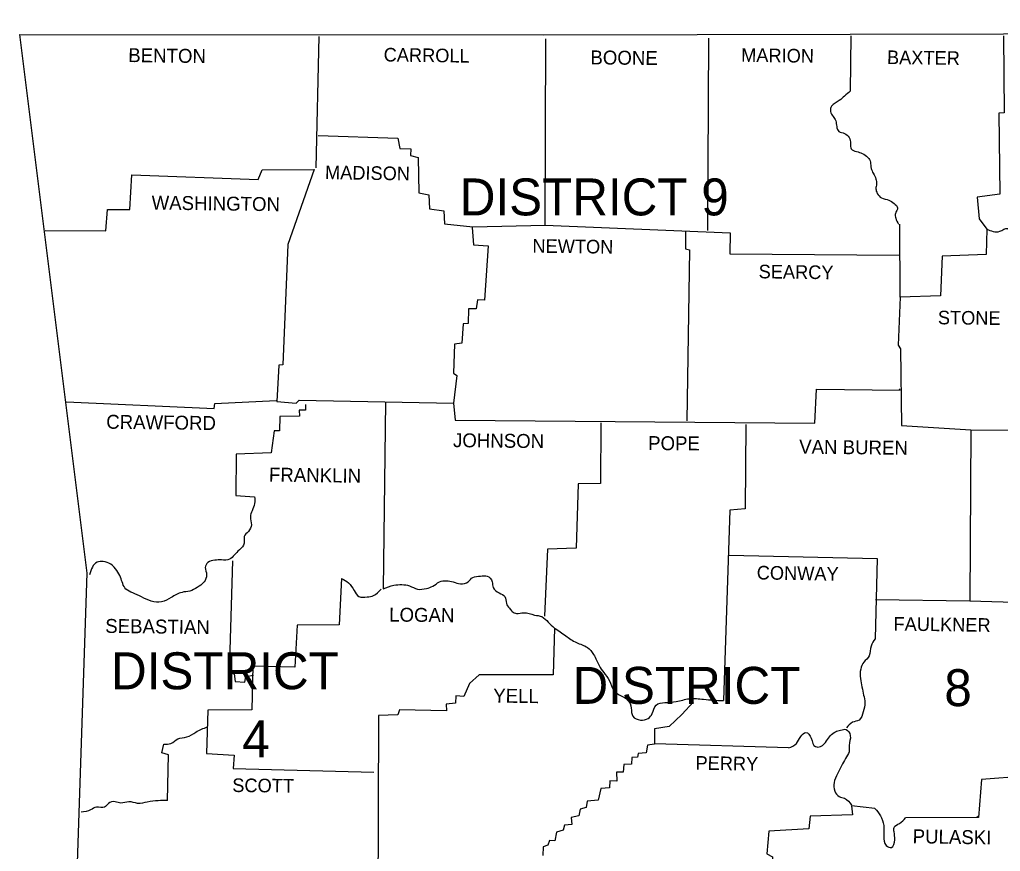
# Model space of a CAD drawing. Extents: x -984 to 3998, y 83 to 2143.
# Drawn here: x 2703.7 to 2999.8, y 1677.5 to 1928.6 of the extents above; entities that cross this region are included whole.
import ezdxf

# ---------------------------------------------------------------- set-up
doc = ezdxf.new("R2010")
doc.units = 0
for name, color, linetype in [('Level 1', 7, 'Continuous'), ('Level 2', 7, 'Continuous'), ('Level 3', 7, 'Continuous')]:
    doc.layers.add(name, color=color, linetype=linetype)

msp = doc.modelspace()

# ---------------------------------------------------------------- linework, layer by layer
at = {"layer": 'Level 1'}
for points in [[(2703.71, 1924.06), (2861.92, 1923.96), (3000.75, 1924.25), (3164.54, 1926.8), (3240.46, 1928.56)], [(2703.71, 1924.06), (2723.96, 1761.45), (2715.15, 1496.01)], [(2794.01, 1923.47), (2793.13, 1883.85)], [(2793.82, 1893.53), (2817.89, 1892.75), (2818.47, 1889.62), (2821.8, 1889.52), (2821.7, 1887.56), (2824.05, 1886.98), (2824.25, 1876.31), (2827.28, 1875.63), (2827.48, 1871.42), (2831.78, 1870.83), (2831.98, 1866.92), (2840.49, 1866.04), (2862.4, 1866.53), (2862.6, 1922.79)], [(2911.62, 1922.98), (2911.33, 1864.87)], [(2954.67, 1923.67), (2954.47, 1906.94)], [(3000.75, 1923.67), (3000.95, 1900.38), (2999.28, 1900.28), (2999.58, 1875.92), (2992.73, 1874.94), (2993.32, 1868.39), (2995.66, 1865.35), (2995.47, 1857.63), (2982.16, 1857.14), (2981.67, 1845.2), (2969.54, 1844.81), (2968.95, 1830.33), (2969.64, 1829.15), (2969.93, 1806.06), (2990.87, 1804.69), (2990.58, 1753.13), (3007.21, 1752.64), (3007.21, 1700.2), (2994.1, 1699.22), (2993.12, 1687.68), (2971.11, 1687.58)], [(2711.44, 1864.87), (2729.73, 1864.77), (2730.22, 1871.23), (2736.97, 1871.23), (2737.56, 1881.69), (2775.72, 1880.32), (2776.89, 1883.26), (2792.64, 1883.36), (2784.72, 1860.66), (2783.15, 1824.36), (2781.98, 1824.26), (2781.39, 1813.3), (2787.17, 1812.81), (2788.05, 1813.69), (2834.72, 1812.81), (2835.21, 1807.63)], [(2840.29, 1865.84), (2840.68, 1860.56), (2845.18, 1860.27), (2844.01, 1843.83), (2841.96, 1843.93), (2841.56, 1841.29), (2839.22, 1841.29), (2839.12, 1836.79), (2837.65, 1836.69), (2837.16, 1830.91), (2835.01, 1830.62), (2834.72, 1821.82), (2835.69, 1821.13), (2834.72, 1812.81)], [(2862.4, 1866.53), (2918.17, 1864.18), (2918.08, 1857.82), (2969.25, 1857.43)], [(2969.54, 1844.81), (2969.44, 1866.82)], [(2904.77, 1864.47), (2904.67, 1859.39), (2905.94, 1859.09), (2905.16, 1807.43)], [(2835.21, 1807.63), (2943.81, 1806.75), (2944.3, 1817.02), (2969.54, 1816.73)], [(2969.25, 1816.83), (2969.54, 1817.12)], [(2717.89, 1813.21), (2762.41, 1811.15), (2762.61, 1812.72), (2781.2, 1813.6)], [(2790, 1812.42), (2790, 1810.66), (2788.14, 1810.66), (2788.24, 1808.9), (2782.27, 1808.8), (2782.18, 1804.4), (2780.51, 1804.4), (2779.63, 1797.84), (2769.06, 1797.36), (2768.97, 1784.93), (2774.64, 1784.54)], [(2814.17, 1813.21), (2813.48, 1756.75)], [(2879.14, 1806.85), (2879.04, 1788.55), (2872.29, 1788.45), (2871.7, 1768.98), (2863.09, 1768.69), (2862.11, 1748.53)], [(2922.97, 1806.36), (2922.77, 1780.92), (2918.08, 1780.53), (2916.22, 1723)], [(2990.87, 1804.69), (3041.16, 1804.4), (3045.46, 1806.45), (3045.17, 1768.2), (3042.24, 1766.93), (3039.59, 1764.68), (3038.71, 1763.8), (3038.62, 1752.84), (3006.62, 1752.84)], [(2767.99, 1765.17), (2767.01, 1731.51), (2768.48, 1731.12), (2768.77, 1728.77), (2771.71, 1728.57), (2772, 1730.24), (2774.35, 1730.63)], [(2917.88, 1766.93), (2962.59, 1765.85), (2962.01, 1741.68)], [(2800.86, 1759.88), (2800.18, 1745.89), (2787.46, 1745.79), (2786.77, 1733.07), (2774.15, 1733.37), (2773.76, 1720.26), (2760.55, 1720.16), (2760.16, 1707.05), (2768.48, 1706.56), (2768.18, 1702.55), (2810.65, 1701.37)], [(2962.1, 1753.52), (2990.58, 1753.13)], [(2865.14, 1744.91), (2864.75, 1730.82), (2842.45, 1730.73), (2839.51, 1728.18), (2837.85, 1724.27), (2835.4, 1724.46), (2835.3, 1722.21), (2832.47, 1721.92), (2832.56, 1719.87), (2818.38, 1720.26), (2817.89, 1718.69), (2812.02, 1718.5), (2811.82, 1661.26)], [(2907.12, 1722.61), (2903.6, 1718.79), (2899.78, 1715.17), (2895.38, 1714.48), (2895.38, 1709.89), (2893.22, 1709.59), (2892.83, 1707.24), (2890.39, 1707.05), (2890.19, 1705.97), (2888.53, 1705.87), (2888.43, 1703.82), (2886.08, 1703.72), (2885.89, 1701.37), (2883.93, 1701.37), (2884.03, 1698.63), (2881.88, 1698.83), (2881.78, 1696.68), (2879.14, 1696.48), (2878.35, 1692.96), (2875.03, 1692.67), (2874.73, 1690.71), (2872.97, 1690.22), (2872.48, 1688.17), (2870.23, 1687.68), (2870.43, 1685.62), (2868.18, 1685.43), (2867.79, 1683.86), (2865.73, 1683.27), (2865.24, 1680.63), (2863.68, 1680.73), (2863.19, 1679.36), (2861.72, 1678.87), (2861.62, 1676.23)], [(2748.32, 1692.86), (2748.62, 1706.66), (2746.66, 1707.24), (2747.25, 1709.89)], [(2935.79, 1708.71), (2895.47, 1709.98)], [(2961.91, 1690.42), (2954.86, 1691.2), (2955.16, 1688.56), (2942.34, 1688.07), (2941.95, 1684.25), (2929.91, 1683.57), (2929.23, 1676.72), (2930.99, 1675.84), (2930.99, 1671.34)], [(2992.63, 1687.77), (2993.12, 1688.26)]]:
    msp.add_lwpolyline(points, dxfattribs=at)
for points in [[(2954.47, 1906.94), (2952.71, 1905.47), (2951.15, 1904.1), (2948.8, 1902.44), (2948.5, 1900.87), (2949.29, 1899.31), (2950.07, 1898.03), (2950.36, 1896.27), (2951.05, 1894.8), (2952.71, 1894.22), (2954.08, 1892.95), (2954.57, 1891.18), (2954.77, 1889.52), (2956.33, 1888.74), (2958.09, 1888.15), (2959.76, 1886.98), (2960.54, 1885.51), (2960.73, 1883.65), (2961.42, 1882.18), (2962.2, 1880.42), (2962.4, 1878.95), (2962.2, 1877.49), (2962.59, 1876.12), (2963.87, 1874.75), (2966.12, 1874.06), (2967.68, 1873.08), (2968.76, 1871.71), (2968.07, 1870.05), (2968.17, 1868.58), (2969.05, 1866.82)], [(2995.66, 1865.35), (2999.58, 1864.67), (3001.93, 1865.55), (3003.59, 1863.01), (3004.47, 1861.05), (3005.94, 1858.21), (3008.29, 1857.33), (3010.05, 1855.77), (3010.05, 1854.1), (3008.48, 1852.54), (3007.31, 1850.97), (3007.7, 1849.11), (3008.09, 1846.57), (3008.09, 1844.12), (3007.5, 1841.87), (3007.01, 1839.82), (3007.5, 1838.06), (3009.36, 1838.35), (3011.32, 1839.82), (3013.37, 1839.82), (3015.33, 1838.74), (3017.38, 1836.88), (3019.44, 1837.27), (3021.1, 1837.76), (3023.45, 1838.45), (3025.11, 1837.57), (3026.58, 1836.39), (3028.34, 1834.53), (3030.01, 1833.36), (3032.16, 1832.28), (3034.8, 1831.6), (3037.25, 1829.94), (3037.64, 1827.1), (3037.54, 1824.65), (3037.34, 1821.62), (3037.15, 1818.29), (3037.44, 1815.06), (3038.52, 1812.91), (3039.89, 1810.37), (3040.28, 1808.02), (3040.18, 1804.3)], [(2774.64, 1784.54), (2774.64, 1782.48), (2773.86, 1780.33), (2773.37, 1778.47), (2773.66, 1776.03), (2772.78, 1774.07), (2771.51, 1772.5), (2771.51, 1770.55), (2770.04, 1768.49), (2768.48, 1766.93), (2767.11, 1765.66), (2764.66, 1765.46), (2762.61, 1765.36), (2760.55, 1764.68), (2759.77, 1763.21), (2760.16, 1760.96), (2759.38, 1758.81), (2757.32, 1757.14), (2755.07, 1756.07), (2752.73, 1755.68), (2749.5, 1754.11), (2746.56, 1752.84), (2743.43, 1753.03), (2740.5, 1754.31), (2737.85, 1755.48), (2735.8, 1756.65), (2734.14, 1760.27), (2733.06, 1762.23), (2731.2, 1764.19), (2728.95, 1764.97), (2727.09, 1764.77), (2724.84, 1760.96)], [(2800.86, 1759.88), (2803.02, 1758.51), (2804.68, 1756.26), (2806.15, 1754.4), (2808.59, 1754.31), (2810.55, 1754.7), (2812.8, 1756.65)], [(2813.48, 1756.75), (2816.71, 1757.83), (2819.06, 1758.02), (2821.41, 1757.63), (2823.86, 1756.65), (2826.5, 1756.85), (2828.45, 1757.53), (2830.41, 1758.81), (2832.56, 1759.2), (2834.62, 1758.81), (2836.77, 1758.22), (2839.12, 1758.9), (2840.49, 1760.18), (2842.84, 1760.57), (2844.89, 1760.57), (2846.36, 1758.9), (2846.65, 1757.14), (2848.51, 1755.48), (2850.17, 1754.4), (2850.66, 1752.35), (2851.54, 1750.88), (2852.43, 1749.9), (2853.7, 1749.32), (2855.85, 1749.51), (2859.18, 1748.83), (2861.33, 1748.34), (2863.29, 1746.67), (2865.14, 1744.91)], [(2865.14, 1744.91), (2868.57, 1742.56), (2871.8, 1740.51), (2875.12, 1739.04), (2876.98, 1736.89), (2878.65, 1733.56), (2880.02, 1731.51), (2881.78, 1728.96), (2883.05, 1726.13), (2885.1, 1724.56), (2887.26, 1723.19), (2888.33, 1720.75), (2888.82, 1718.3), (2891.17, 1717.13), (2893.42, 1717.62), (2894.69, 1719.08), (2895.87, 1721.63), (2898.51, 1722.41), (2901.93, 1722.7), (2905.85, 1723.58), (2910.15, 1723.39), (2916.22, 1723)], [(2962.01, 1741.68), (2960.73, 1739.43), (2960.15, 1736.5), (2958.58, 1734.64), (2957.6, 1732.49), (2957.51, 1729.65), (2958, 1727.11), (2958.48, 1724.66), (2958.88, 1722.41), (2958.39, 1719.57), (2957.11, 1717.13), (2955.16, 1716.44), (2953.3, 1714.78)], [(2747.25, 1709.89), (2749.4, 1710.08), (2751.45, 1711.45), (2754.19, 1712.04), (2756.93, 1713.51), (2760.36, 1715.07)], [(2935.79, 1708.71), (2938.23, 1710.08), (2939.5, 1712.14), (2941.07, 1713.41), (2942.63, 1711.65), (2944, 1709.1), (2945.47, 1709.1), (2947.33, 1710.86), (2948.5, 1712.43), (2949.97, 1713.6), (2951.54, 1714.09), (2953.2, 1714.29), (2954.47, 1712.43), (2954.08, 1709.49), (2954.08, 1707.54), (2953.01, 1705.48), (2951.83, 1703.33), (2950.56, 1700.88), (2949.58, 1698.24), (2949.78, 1695.7), (2951.15, 1694.04), (2952.71, 1693.55), (2954.86, 1691.39)], [(2748.32, 1692.86), (2745.49, 1692.76), (2742.26, 1692.37), (2739.32, 1691.98), (2736.68, 1692.47), (2734.23, 1692.08), (2732.57, 1692.47), (2730.52, 1691.98), (2729.34, 1690.81), (2726.9, 1690.81), (2725.13, 1690.02), (2722.3, 1689.34)], [(2961.91, 1690.42), (2963.57, 1688.26), (2964.55, 1685.33), (2964.55, 1682), (2965.33, 1679.26), (2966.9, 1678.67), (2967.88, 1681.02), (2967.68, 1683.37), (2967.68, 1684.74), (2969.34, 1685.91), (2971.11, 1687.58)]]:
    msp.add_spline(points, degree=3, dxfattribs=at)

# ---------------------------------------------------------------- texts
at = {"layer": 'Level 2'}
for s, height, rotation, p in [('BENTON', 4.207, 359.2527, (2736.48, 1915.74)), ('CARROLL', 4.109, 359.1481, (2813.58, 1915.94)), ('BOONE', 4.207, 359.4001, (2876, 1915.06)), ('MARION', 4.109, 359.1854, (2921.5, 1915.84)), ('BAXTER', 4.109, 359.2559, (2965.53, 1915.16)), ('MADISON', 4.109, 359.0906, (2795.87, 1880.42)), ('WASHINGTON', 4.206, 359.232, (2743.53, 1871.23)), ('NEWTON', 4.109, 359.2717, (2858.49, 1858.21)), ('SEARCY', 4.108, 359.2527, (2926.78, 1850.48)), ('STONE', 4.108, 359.4001, (2980.89, 1836.59)), ('CRAWFORD', 4.206, 359.2771, (2729.83, 1805.08)), ('JOHNSON', 4.207, 359.3514, (2834.52, 1799.51)), ('POPE', 4.207, 359.6155, (2893.42, 1798.63)), ('VAN BUREN', 4.207, 359.3508, (2939.01, 1797.55)), ('FRANKLIN', 4.207, 359.1815, (2778.95, 1789.14)), ('CONWAY', 4.108, 359.0371, (2926.2, 1759.59)), ('LOGAN', 4.207, 359.3969, (2815.25, 1746.87)), ('SEBASTIAN', 4.206, 359.2816, (2729.54, 1743.45)), ('FAULKNER', 4.109, 359.2486, (2967.49, 1744.13)), ('YELL', 4.207, 359.1987, (2846.65, 1722.41)), ('PERRY', 4.109, 359.0858, (2907.71, 1702.16)), ('SCOTT', 4.109, 359.4063, (2767.89, 1695.41)), ('PULASKI', 4.207, 359.053, (2973.26, 1679.95))]:
    msp.add_text(s, height=height, rotation=rotation, dxfattribs=at).set_placement(p)
at = {"layer": 'Level 3'}
for s, height, p in [('DISTRICT 9', 11.154, (2836.57, 1869.46)), ('DISTRICT', 11.154, (2731.3, 1726.42)), ('DISTRICT', 11.154, (2870.62, 1722.02)), ('8', 11.15, (2982.85, 1721.33)), ('4', 11.15, (2770.92, 1705.87))]:
    msp.add_text(s, height=height, dxfattribs=at).set_placement(p)

doc.saveas('drawing.dxf')
